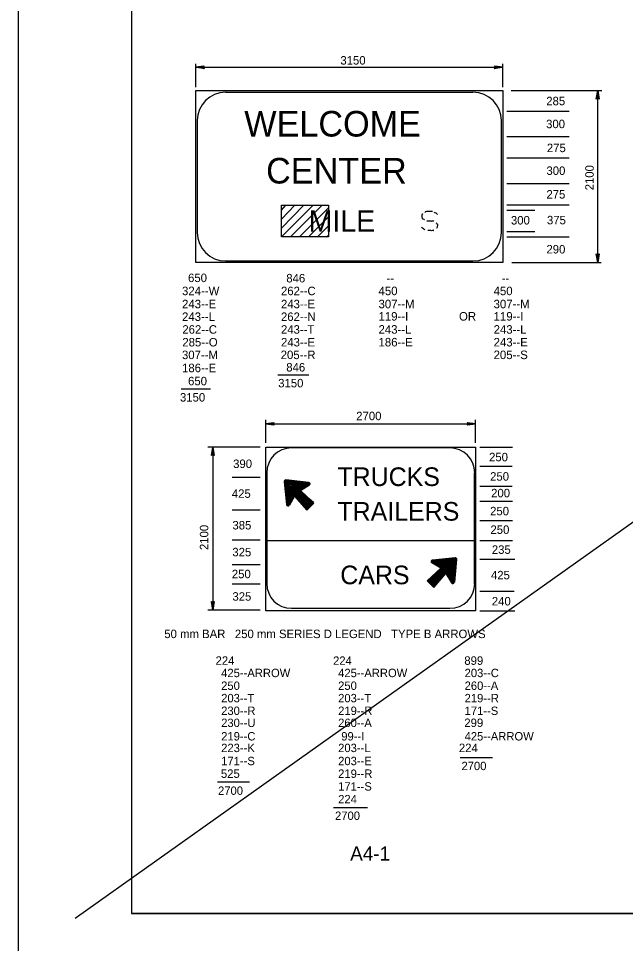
# Model space of a CAD drawing. Extents: x 2189973 to 2192941, y 2147557 to 2151454.
# Drawn here: x 2189973 to 2190678, y 2149520 to 2150594 of the extents above; entities that cross this region are included whole.
import ezdxf

# ---------------------------------------------------------------- set-up
doc = ezdxf.new("R2010")
doc.units = 0
for name, color, linetype in [('1', 7, 'Continuous'), ('Default', 7, 'Continuous'), ('PLT-BNDY', 7, 'Continuous')]:
    doc.layers.add(name, color=color, linetype=linetype)

# ---------------------------------------------------------------- blocks, each defined once
blk = doc.blocks.new('RARROW')
at = {"layer": 'Default'}
blk.add_lwpolyline([(-18.156, 2.28), (-17.479, 0.966), (0, 0), (-18.156, 2.28), (-19.086, 3.077), (0, 0), (-17.465, -0.864), (-18.103, -2.164), (0, 0), (-19.086, -3.033), (-18.103, -2.164)], dxfattribs=at)

msp = doc.modelspace()

# ---------------------------------------------------------------- linework, layer by layer
at = {"layer": '1'}
msp.add_line((2192688.3, 2151431), (2190039.1, 2149549), dxfattribs=at)
at = {"layer": 'Default'}
for p, q in [((2190104.5, 2151405.2), (2190104.5, 2149554.8)), ((2190179.1, 2150514), (2190179.1, 2150541.1)), ((2190179.1, 2150537), (2190535.5, 2150537)), ((2190535.5, 2150514), (2190535.5, 2150541.1)), ((2190179.1, 2150509.9), (2190535.5, 2150509.9)), ((2190179.1, 2150310.6), (2190179.1, 2150509.9)), ((2190500.6, 2150507.9), (2190213.6, 2150507.9)), ((2190535.5, 2150509.9), (2190535.5, 2150310.6)), ((2190545.3, 2150509.9), (2190650.5, 2150509.9)), ((2190645.6, 2150310.6), (2190645.6, 2150509.9)), ((2190540, 2150486.2), (2190612.5, 2150486.2)), ((2190180.8, 2150474.7), (2190180.8, 2150345.5)), ((2190533.9, 2150345.5), (2190533.9, 2150474.7)), ((2190540, 2150456.6), (2190612.5, 2150456.6)), ((2190540, 2150432), (2190612.5, 2150432)), ((2190540, 2150402.1), (2190612.5, 2150402.1)), ((2190540, 2150377.5), (2190612.5, 2150377.5)), ((2190540, 2150371.3), (2190572.8, 2150371.3)), ((2190540, 2150346.3), (2190572.8, 2150346.3)), ((2190540, 2150340.2), (2190612.5, 2150340.2)), ((2190535.5, 2150310.6), (2190179.1, 2150310.6)), ((2190213.6, 2150312.3), (2190500.6, 2150312.3)), ((2190545.8, 2150310.6), (2190649.7, 2150310.6)), ((2190274.3, 2150180.2), (2190310.4, 2150180.2)), ((2190161.9, 2150163.8), (2190196.3, 2150163.8)), ((2190260.3, 2150101.1), (2190260.3, 2150127.7)), ((2190503.9, 2150101.1), (2190503.9, 2150127.7)), ((2190260.3, 2150123.2), (2190503.9, 2150123.2)), ((2190253.7, 2150096.1), (2190193, 2150096.1)), ((2190198.8, 2150096.1), (2190198.8, 2149907.1)), ((2190508.8, 2150096.1), (2190546.8, 2150096.1)), ((2190260.3, 2150070.3), (2190260.3, 2150088.3)), ((2190508.8, 2150074), (2190546.2, 2150074)), ((2190253.7, 2150060.9), (2190221.3, 2150060.9)), ((2190261.5, 2150066.2), (2190261.5, 2149937.4)), ((2190502.6, 2149937.4), (2190502.6, 2150066.2)), ((2190281.6, 2150055.9), (2190284.5, 2150029.7)), ((2190282, 2150057.2), (2190282, 2150057.2)), ((2190282, 2150057.2), (2190282, 2150057.2)), ((2190310.3, 2150055.1), (2190283.6, 2150058)), ((2190283.6, 2150056.4), (2190283.6, 2150056.4)), ((2190300.5, 2150045.7), (2190311.1, 2150052.2)), ((2190309.5, 2150053.5), (2190309.5, 2150053.5)), ((2190312.4, 2150053.5), (2190312.4, 2150053.5)), ((2190312.4, 2150053.5), (2190312.4, 2150053.5)), ((2190508.8, 2150051), (2190546.2, 2150051)), ((2190293.5, 2150039.1), (2190287.7, 2150028.9)), ((2190293.5, 2150039.1), (2190293.5, 2150039.1)), ((2190293.5, 2150039.1), (2190307.8, 2150023.1)), ((2190297.2, 2150042.4), (2190297.2, 2150042.4)), ((2190300.5, 2150045.7), (2190300.5, 2150045.7)), ((2190316, 2150031.3), (2190300.5, 2150045.7)), ((2190286.5, 2150029.7), (2190286.5, 2150029.7)), ((2190286.5, 2150027.2), (2190286.5, 2150027.2)), ((2190286.5, 2150027.2), (2190286.5, 2150027.2)), ((2190307.8, 2150023.1), (2190316, 2150031.3)), ((2190316, 2150031.3), (2190316, 2150031.3)), ((2190508.8, 2150033.4), (2190546.8, 2150033.4)), ((2190253.7, 2150023.1), (2190221.3, 2150023.1)), ((2190307.8, 2150023.1), (2190307.8, 2150023.1)), ((2190508.8, 2150010.8), (2190546.8, 2150010.8)), ((2190260.3, 2149983.4), (2190260.3, 2149995.2)), ((2190253.7, 2149988.3), (2190221.3, 2149988.3)), ((2190260.3, 2149987.9), (2190502.6, 2149987.9)), ((2190508.8, 2149987.9), (2190546.8, 2149987.9)), ((2190451.8, 2149962.8), (2190451.8, 2149962.8)), ((2190451.8, 2149962.8), (2190451.8, 2149962.8)), ((2190480.1, 2149967.8), (2190453.8, 2149964.9)), ((2190453.8, 2149962.8), (2190453.8, 2149962.8)), ((2190479.7, 2149939.5), (2190482.1, 2149965.7)), ((2190480.1, 2149965.7), (2190480.1, 2149965.7)), ((2190508.8, 2149966.1), (2190549.3, 2149966.1)), ((2190253.7, 2149959.6), (2190221.3, 2149959.6)), ((2190463.7, 2149955.5), (2190447.7, 2149941.1)), ((2190463.7, 2149955.5), (2190453, 2149962)), ((2190463.7, 2149955.5), (2190463.7, 2149955.5)), ((2190466.6, 2149952.2), (2190466.6, 2149952.2)), ((2190455.5, 2149933.3), (2190469.4, 2149949.3)), ((2190469.4, 2149949.3), (2190469.4, 2149949.3)), ((2190469.4, 2149949.3), (2190476, 2149938.7)), ((2190253.7, 2149937), (2190221.3, 2149937)), ((2190447.7, 2149941.1), (2190447.7, 2149941.1)), ((2190447.7, 2149941.1), (2190455.5, 2149933.3)), ((2190455.5, 2149933.3), (2190455.5, 2149933.3)), ((2190477.6, 2149939.9), (2190477.6, 2149939.9)), ((2190477.6, 2149937.4), (2190477.6, 2149937.4)), ((2190477.6, 2149937.4), (2190477.6, 2149937.4)), ((2190508.8, 2149928.8), (2190548.7, 2149928.8)), ((2190253.7, 2149907.1), (2190193, 2149907.1)), ((2190508.8, 2149906.3), (2190549.3, 2149906.3)), ((2190485.8, 2149736.1), (2190523.6, 2149736.1)), ((2190204.1, 2149707.8), (2190241.4, 2149707.8)), ((2190339, 2149677.8), (2190378.4, 2149677.8)), ((2192683.2, 2149554.8), (2190104.5, 2149554.8)), ((2190104.5, 2149554.8), (2192027, 2149554.8))]:
    msp.add_line(p, q, dxfattribs=at)
msp.add_lwpolyline([(2190278.4, 2150340.2), (2190278.4, 2150377.1), (2190333.3, 2150377.1), (2190333.3, 2150340.2)], close=True, dxfattribs=at)
for points in [[(2190278.4, 2150340.2), (2190315.3, 2150377.1)], [(2190278.4, 2150350.4), (2190304.6, 2150377.1)], [(2190278.4, 2150360.7), (2190293.9, 2150377.1)], [(2190278.4, 2150371.3), (2190283.7, 2150377.1)], [(2190289, 2150340.2), (2190325.9, 2150377.1)], [(2190299.3, 2150340.2), (2190333.3, 2150373.8)], [(2190309.9, 2150340.2), (2190333.3, 2150363.5)], [(2190320.2, 2150340.2), (2190333.3, 2150352.9)], [(2190330.9, 2150340.2), (2190333.3, 2150342.2)], [(2190260.3, 2150096.1), (2190503.9, 2150096.1), (2190503.9, 2150079.3), (2190503.9, 2150057.6), (2190503.9, 2150041.2), (2190503.9, 2150019.4), (2190503.9, 2150002.6), (2190503.9, 2149986.6), (2190503.9, 2149950.5), (2190503.9, 2149906.3), (2190260.3, 2149906.3), (2190260.3, 2149957.1), (2190260.3, 2149979.3), (2190260.3, 2150002.6), (2190260.3, 2150030.9), (2190260.3, 2150066.2), (2190260.3, 2150096.1)], [(2190473.9, 2150095.3), (2190290.6, 2150095.3)], [(2190282.8, 2150056.4), (2190285.3, 2150030.1), (2190285.3, 2150028.9), (2190286.9, 2150028.1), (2190287.3, 2150028.9), (2190293.5, 2150040.8), (2190294.7, 2150039.9), (2190308.3, 2150024.4), (2190315.6, 2150031.7), (2190299.6, 2150045.3), (2190300.1, 2150046.1), (2190311.1, 2150052.7), (2190311.9, 2150053.5), (2190311.5, 2150054.3), (2190310.3, 2150054.3), (2190283.6, 2150057.2), (2190282.8, 2150057.2), (2190282.8, 2150056.4), (2190283.2, 2150056.4), (2190286.5, 2150028.9), (2190293.5, 2150041.2), (2190308.3, 2150025.2), (2190314.8, 2150031.3), (2190298.8, 2150046.1), (2190311.5, 2150053.5), (2190283.2, 2150056.8), (2190286.9, 2150030.5), (2190293.5, 2150042), (2190308.3, 2150025.6), (2190314.4, 2150031.3), (2190298, 2150046.1), (2190310.3, 2150053.5), (2190283.6, 2150056.4), (2190286.9, 2150031.3), (2190293.5, 2150042.4), (2190308.7, 2150026.4), (2190313.6, 2150031.3), (2190297.6, 2150046.1), (2190308.7, 2150053.5), (2190284.1, 2150055.9), (2190286.9, 2150033), (2190293.5, 2150042.4), (2190308.7, 2150027.2), (2190312.8, 2150031.3), (2190297.2, 2150046.5), (2190307.8, 2150053.1), (2190284.5, 2150055.1), (2190287.3, 2150034.2), (2190293.5, 2150042.8), (2190308.7, 2150028.1), (2190312.4, 2150031.7), (2190296.8, 2150046.5), (2190306.6, 2150052.2), (2190285.3, 2150054.3), (2190288.2, 2150035.4), (2190293.5, 2150043.2), (2190308.7, 2150028.9), (2190311.9, 2150031.7), (2190296.8, 2150046.5), (2190305, 2150051.4), (2190285.7, 2150054.3), (2190288.6, 2150037.5), (2190293.5, 2150044.5), (2190308.7, 2150029.7), (2190311.1, 2150031.7), (2190296.4, 2150046.5), (2190304.2, 2150051), (2190286.5, 2150053.5), (2190289, 2150038.7), (2190293.1, 2150045.3), (2190308.7, 2150030.5), (2190310.3, 2150031.7), (2190295.5, 2150046.5), (2190302.5, 2150050.6), (2190286.9, 2150053.1), (2190289, 2150039.5), (2190293.1, 2150045.7), (2190308.7, 2150030.9), (2190309.5, 2150031.7), (2190295.1, 2150046.5), (2190300.9, 2150050.6), (2190287.7, 2150052.7), (2190289, 2150041.2), (2190293.1, 2150046.5), (2190308.7, 2150031.3), (2190308.7, 2150031.3), (2190294.3, 2150046.5), (2190299.6, 2150050.2), (2190288.6, 2150051.4), (2190289.4, 2150042.4), (2190293.1, 2150046.5), (2190308.7, 2150031.3), (2190293.5, 2150046.9), (2190298.4, 2150050.2), (2190289, 2150051), (2190289.8, 2150043.2), (2190293.1, 2150046.9), (2190300.5, 2150039.9), (2190293.1, 2150047.3), (2190297.6, 2150049.8), (2190289.4, 2150050.6)], [(2190289.4, 2150050.6), (2190290.6, 2150045.3), (2190296.8, 2150049.4), (2190289.8, 2150050.2), (2190291, 2150046.1), (2190296, 2150049.4), (2190290.6, 2150049.4), (2190291, 2150046.5), (2190294.3, 2150049.4), (2190291, 2150049.4), (2190291, 2150047.3), (2190293.1, 2150049), (2190291, 2150049), (2190291.4, 2150049), (2190292.3, 2150049)], [(2190480.1, 2149966.9), (2190454.3, 2149964.1), (2190453, 2149964.1), (2190452.6, 2149962.8), (2190453, 2149962.4), (2190464.5, 2149955.5), (2190464.5, 2149955.5), (2190448.5, 2149941.1), (2190455.9, 2149933.7), (2190469, 2149949.3), (2190469.8, 2149949.3), (2190476.4, 2149938.7), (2190477.6, 2149937.8), (2190478, 2149938.7), (2190478.4, 2149939.5), (2190481.3, 2149966.1), (2190481.3, 2149966.5), (2190480.5, 2149967.4), (2190480.1, 2149966.1), (2190453, 2149963.3), (2190465.3, 2149955.5), (2190448.9, 2149941.1), (2190455.5, 2149933.7), (2190469.8, 2149951), (2190477.6, 2149938.7), (2190480.9, 2149966.5), (2190454.3, 2149962.8), (2190465.7, 2149955.5), (2190449.7, 2149941.1), (2190455.5, 2149935.4), (2190469.8, 2149951.4), (2190477.2, 2149939.9), (2190480.1, 2149965.7), (2190455.5, 2149962.8), (2190466.1, 2149955.5), (2190450.6, 2149941.1), (2190455.5, 2149936.2), (2190469.8, 2149951.8), (2190477.2, 2149940.7), (2190480.1, 2149964.9), (2190456.7, 2149962.4), (2190466.6, 2149955.9), (2190451.8, 2149941.1), (2190455.5, 2149937), (2190469.8, 2149952.2), (2190476.8, 2149941.5), (2190479.7, 2149964.9), (2190458.4, 2149962.4), (2190467.8, 2149955.9), (2190452.6, 2149941.1), (2190455.9, 2149937.4), (2190469.8, 2149953), (2190476, 2149943.2), (2190478.4, 2149964.1), (2190460.4, 2149962), (2190468.2, 2149955.9), (2190453, 2149941.1), (2190455.9, 2149937.8), (2190469.8, 2149953), (2190476, 2149944.4), (2190478, 2149963.7), (2190461.6, 2149961.2), (2190468.6, 2149955.9), (2190453.8, 2149941.1), (2190455.9, 2149939.1), (2190470.2, 2149953.4), (2190476, 2149945.6), (2190477.6, 2149963.3), (2190462.5, 2149960.8), (2190469, 2149955.9), (2190454.3, 2149941.1), (2190455.9, 2149939.9), (2190470.2, 2149954.2), (2190475.6, 2149947.3), (2190476.8, 2149962.8), (2190464.1, 2149960.8), (2190469.4, 2149955.9), (2190454.7, 2149941.1), (2190455.9, 2149939.9), (2190470.2, 2149955.1), (2190474.8, 2149948.5), (2190476.4, 2149962.4), (2190465.3, 2149960.8), (2190469.8, 2149955.9), (2190455.5, 2149941.1), (2190455.5, 2149940.3), (2190470.7, 2149955.5), (2190474.3, 2149950.1), (2190476, 2149961.2), (2190466.6, 2149960.4), (2190470.2, 2149956.3), (2190455.5, 2149940.7), (2190471.5, 2149955.9), (2190474.3, 2149951.4), (2190476, 2149960.8), (2190468.2, 2149960), (2190471.5, 2149956.3), (2190464.5, 2149949.3), (2190471.9, 2149956.3), (2190473.9, 2149951.8), (2190475.6, 2149960.4)], [(2190475.6, 2149960.4), (2190469, 2149959.6), (2190473.5, 2149953), (2190474.3, 2149960), (2190469.8, 2149959.2), (2190473.5, 2149953.4), (2190473.5, 2149959.2), (2190470.7, 2149958.7), (2190473.1, 2149955.5), (2190473.1, 2149958.7), (2190471.9, 2149958.3), (2190472.7, 2149955.9), (2190472.7, 2149958.3), (2190472.7, 2149958.3), (2190472.7, 2149957.1)], [(2190290.6, 2149909.1), (2190473.9, 2149909.1)]]:
    msp.add_lwpolyline(points, dxfattribs=at)
for centre, radius, start, end in [((2190213.8, 2150475.1), 33, 90, 180), ((2190500.8, 2150475.1), 33, 0, 90), ((2190213.8, 2150345.2), 33, 180, 270), ((2190500.8, 2150345.2), 33, 270, 0), ((2190290.1, 2150066.5), 28.7, 90, 180), ((2190474.1, 2150066.5), 28.7, 0, 90), ((2190283.4, 2150056.2), 1.69, 84.0498, 185.9502), ((2190310, 2150053.4), 1.69, 301.5539, 84.0498), ((2190286.2, 2150029.6), 1.69, 185.9502, 328.4461), ((2190453.8, 2149963.2), 1.69, 95.9502, 238.4461), ((2190480.3, 2149966), 1.69, 354.0498, 95.9502), ((2190290.1, 2149937.8), 28.7, 180, 270), ((2190474.1, 2149937.8), 28.7, 270, 0), ((2190477.5, 2149939.5), 1.69, 211.5539, 354.0498)]:
    msp.add_arc(centre, radius, start, end, dxfattribs=at)
for points in [[(2190442.4, 2150366.8), (2190442, 2150366.4), (2190441.6, 2150366), (2190441.6, 2150363.1), (2190442, 2150361.5), (2190443.6, 2150360.7), (2190444.5, 2150359.8)], [(2190453.9, 2150369.7), (2190453.1, 2150369.7), (2190451.8, 2150369.7), (2190447.7, 2150369.7), (2190446.9, 2150369.7), (2190444.9, 2150368.5)], [(2190459.6, 2150366), (2190458, 2150367.6), (2190455.9, 2150368.5)], [(2190444.9, 2150348.4), (2190444.5, 2150348.8), (2190443.2, 2150349.6), (2190441.2, 2150351.2)], [(2190447.3, 2150358.6), (2190448.6, 2150358.6), (2190450.2, 2150358.6), (2190452.2, 2150358.6), (2190453.9, 2150358.6), (2190455.1, 2150358.6), (2190455.5, 2150358.2)], [(2190458, 2150356.6), (2190458.8, 2150355.7), (2190459.2, 2150354.9), (2190459.6, 2150354.5), (2190459.6, 2150352.9), (2190459.2, 2150351.6), (2190458.4, 2150350)], [(2190454.7, 2150347.5), (2190455.1, 2150347.9), (2190453.9, 2150347.5), (2190451.8, 2150347.5), (2190449.8, 2150347.5), (2190448.6, 2150347.5)]]:
    msp.add_spline(points, degree=3, dxfattribs=at)
at = {"layer": 'PLT-BNDY'}
msp.add_lwpolyline([(2189973.2, 2151454.4), (2192732.4, 2151454.4), (2192732.4, 2149505.6), (2189973.2, 2149505.6)], close=True, dxfattribs=at)

# ---------------------------------------------------------------- block references
at = {"layer": 'Default', "xscale": 0.515679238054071, "yscale": 0.5369477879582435}
for p, rotation in [((2190179.1, 2150537), 180), ((2190645.6, 2150509.9), 89.99999999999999), ((2190645.6, 2150310.6), -90.00000000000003), ((2190260.3, 2150123.2), 180), ((2190198.8, 2150096.1), 89.99999999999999), ((2190198.8, 2149907.1), -90.00000000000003)]:
    msp.add_blockref('RARROW', p, dxfattribs=dict(at, rotation=rotation))
for p in [(2190535.5, 2150537), (2190503.9, 2150123.2)]:
    msp.add_blockref('RARROW', p, dxfattribs=at)

# ---------------------------------------------------------------- texts
at = {"layer": 'Default'}
for s, height, p in [('3150', 9.84, (2190346.9, 2150540.1)), ('285', 9.84, (2190585.9, 2150492.9)), ('300', 9.84, (2190585.7, 2150466.3)), ('275', 9.84, (2190586.6, 2150438.5)), ('300', 9.84, (2190586.1, 2150412.1)), ('275', 9.84, (2190586.1, 2150384.6)), ('300', 9.84, (2190544.9, 2150354.5)), ('375', 9.84, (2190586.7, 2150354.7)), ('290', 9.84, (2190586.1, 2150320.9)), ('650', 9.84, (2190170.1, 2150287.7)), ('846', 9.84, (2190284.1, 2150287.3)), (' 324--W', 9.89, (2190159.4, 2150272.5)), (' 262--C', 9.84, (2190274.3, 2150272.5)), (' 450   ', 9.89, (2190387.5, 2150272.5)), (' 450   ', 9.89, (2190521.1, 2150272.5)), (' 243--E', 9.89, (2190159.4, 2150257.3)), (' 243--E', 9.84, (2190274.3, 2150257.3)), (' 307--M', 9.89, (2190387.5, 2150257.3)), (' 307--M', 9.89, (2190521.1, 2150257.3)), (' 119--I', 9.89, (2190387.5, 2150243)), ('OR', 9.89, (2190484.6, 2150243)), (' 119--I', 9.89, (2190521.1, 2150243)), (' 243--L', 9.89, (2190159.4, 2150242.6)), (' 262--N', 9.84, (2190274.3, 2150242.6)), (' 262--C', 9.84, (2190159.8, 2150227.8)), (' 243--T', 9.84, (2190274.3, 2150227.8)), (' 243--L', 9.89, (2190387.5, 2150227.8)), (' 243--L', 9.89, (2190521.1, 2150227.8)), (' 285--O', 9.84, (2190159.8, 2150213)), (' 243--E', 9.84, (2190274.3, 2150213)), (' 186--E', 9.89, (2190387.5, 2150213)), (' 243--E', 9.89, (2190521.1, 2150213)), (' 307--M', 9.84, (2190159.4, 2150198.3)), (' 205--R', 9.89, (2190273.9, 2150198.3)), (' 205--S', 9.89, (2190521.1, 2150198.3)), (' 186--E', 9.89, (2190159.4, 2150183.1)), ('846', 9.84, (2190284.1, 2150183.9)), ('650', 9.84, (2190170.1, 2150167.9)), ('3150', 9.84, (2190274.7, 2150165.5)), ('3150', 9.84, (2190160.7, 2150149)), ('2700', 9.84, (2190365.3, 2150127.4)), ('390', 9.84, (2190222.4, 2150071.9)), ('250', 9.84, (2190519.5, 2150079.7)), ('250', 9.84, (2190520.7, 2150057.2)), ('425', 9.84, (2190220.9, 2150037.3)), ('200', 9.84, (2190521.9, 2150037.9)), ('250', 9.84, (2190520.7, 2150017)), ('385', 9.84, (2190221.6, 2150000.6)), ('250', 9.84, (2190521.1, 2149995.5)), ('325', 9.84, (2190221.5, 2149969.4)), ('235', 9.84, (2190522.7, 2149972.3)), ('250', 9.84, (2190220.9, 2149944)), ('425', 9.84, (2190521.7, 2149942.7)), ('325', 9.84, (2190221.6, 2149917.9)), ('240', 9.84, (2190522.7, 2149912.4)), ('50 mm BAR   250 mm SERIES D LEGEND   TYPE B ARROWS', 9.842, (2190142.5, 2149874.5)), ('  224        ', 9.842, (2190194.7, 2149843.5)), ('  224        ', 9.732, (2190331.2, 2149843.5)), (' 899       ', 9.842, (2190487.1, 2149843.5)), (' 425--ARROW', 9.732, (2190204.9, 2149829.2)), (' 425--ARROW', 9.732, (2190340.7, 2149829.2)), (' 203--C    ', 9.732, (2190487.5, 2149829.2)), (' 250       ', 9.732, (2190204.9, 2149814.4)), (' 250       ', 9.732, (2190340.7, 2149814.4)), (' 260--A    ', 9.732, (2190487.5, 2149814.4)), (' 203--T    ', 9.732, (2190204.9, 2149800)), (' 203--T    ', 9.732, (2190340.7, 2149800)), (' 219--R    ', 9.732, (2190487.5, 2149800)), (' 230--R    ', 9.732, (2190204.9, 2149785.3)), (' 219--R    ', 9.732, (2190340.7, 2149785.3)), (' 171--S    ', 9.732, (2190487.5, 2149785.3)), (' 230--U    ', 9.732, (2190204.9, 2149771.3)), (' 260--A    ', 9.732, (2190340.7, 2149771.3)), (' 299       ', 9.842, (2190487.1, 2149771.3)), (' 219--C    ', 9.732, (2190204.9, 2149755.7)), ('  99--I    ', 9.732, (2190340.7, 2149755.7)), (' 425--ARROW', 9.732, (2190487.5, 2149755.7)), (' 223--K    ', 9.732, (2190204.9, 2149742.2)), (' 203--L    ', 9.732, (2190340.7, 2149742.2)), ('  224        ', 9.842, (2190477.2, 2149742.2)), (' 171--S    ', 9.732, (2190204.9, 2149727)), (' 203--E    ', 9.732, (2190340.7, 2149727)), ('2700       ', 9.732, (2190487.5, 2149721.3)), (' 525       ', 9.842, (2190204.5, 2149712.3)), (' 219--R    ', 9.732, (2190340.7, 2149712.3)), (' 171--S    ', 9.732, (2190340.7, 2149697.5)), ('2700       ', 9.732, (2190204.9, 2149692.6)), (' 224       ', 9.732, (2190340.7, 2149682.7)), ('2700        ', 9.732, (2190340.7, 2149663.5)), ('A4-1', 16.4, (2190358.3, 2149616.3))]:
    msp.add_text(s, height=height, dxfattribs=at).set_placement(p)
for s, height, rotation, p in [('WELCOME', 29.69, 360, (2190235.3, 2150456.6)), ('CENTER', 29.69, 360, (2190260.7, 2150402.1)), ('2100', 9.84, 90, (2190641, 2150394.2)), ('   MILE', 24.74, 360, (2190282.5, 2150346.3)), ('     -- ', 9.89, 360, (2190382.1, 2150287.3)), ('     -- ', 9.89, 360, (2190515.8, 2150287.3)), ('TRUCKS', 21.64, 360, (2190343.5, 2150051)), ('TRAILERS', 21.64, 360, (2190343.5, 2150010.8)), ('2100', 9.84, 90, (2190193.6, 2149976.7)), ('CARS', 21.64, 360, (2190346.8, 2149937))]:
    msp.add_text(s, height=height, rotation=rotation, dxfattribs=at).set_placement(p)

doc.saveas('drawing.dxf')
